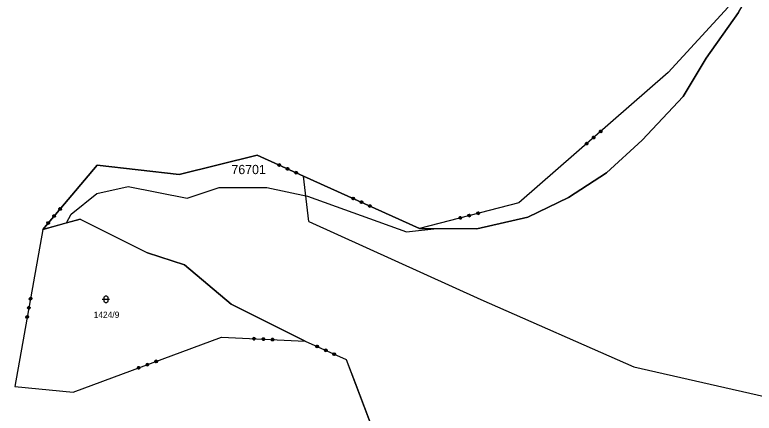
# Model space of a CAD drawing. Extents: x -779618 to -776429, y -1144546 to -1143350.
# Drawn here: x -779618.2 to -779418.1, y -1143697.1 to -1143589.4 of the extents above; entities that cross this region are included whole.
import ezdxf

# ---------------------------------------------------------------- set-up
doc = ezdxf.new("R2010")
doc.units = 0
for name, color, linetype in [('1', 7, 'Continuous'), ('11', 7, 'Continuous'), ('2', 7, 'Continuous'), ('3', 7, 'Continuous')]:
    doc.layers.add(name, color=color, linetype=linetype)

msp = doc.modelspace()

# ---------------------------------------------------------------- linework, layer by layer
at = {"layer": '1'}
for p, q in [((-779425.2, -1143587.3), (-779441.4, -1143604.95)), ((-779422.4, -1143588.74), (-779431.16, -1143601.12)), ((-779431.16, -1143601.12), (-779437.37, -1143611.48)), ((-779441.4, -1143604.95), (-779481.8, -1143640.2)), ((-779437.37, -1143611.48), (-779448.47, -1143623.31)), ((-779448.47, -1143623.31), (-779458.09, -1143632.15)), ((-779552.66, -1143627.32), (-779573.76, -1143632.55)), ((-779540.12, -1143632.98), (-779552.66, -1143627.32)), ((-779595.99, -1143630.06), (-779610.61, -1143647.4)), ((-779573.76, -1143632.55), (-779595.99, -1143630.06)), ((-779458.09, -1143632.15), (-779468.43, -1143638.83)), ((-779538.66, -1143645.32), (-779540.12, -1143632.98)), ((-779508.7, -1143647.15), (-779540.12, -1143632.98)), ((-779481.8, -1143640.2), (-779508.7, -1143647.15)), ((-779468.43, -1143638.83), (-779479.43, -1143644.1)), ((-779600.56, -1143644.61), (-779610.61, -1143647.4)), ((-779600.56, -1143644.61), (-779582.3, -1143653.77)), ((-779479.43, -1143644.1), (-779493.22, -1143647.23)), ((-779538.66, -1143645.32), (-779492.08, -1143666.42)), ((-779610.61, -1143647.4), (-779618.24, -1143689.87)), ((-779493.22, -1143647.23), (-779508.7, -1143647.15)), ((-779572.35, -1143657.01), (-779582.3, -1143653.77)), ((-779559.66, -1143667.6), (-779572.35, -1143657.01)), ((-779492.08, -1143666.42), (-779450.72, -1143684.57)), ((-779539.64, -1143677.6), (-779559.66, -1143667.6)), ((-779602.41, -1143691.41), (-779562.33, -1143676.57)), ((-779562.33, -1143676.57), (-779539.64, -1143677.6)), ((-779539.64, -1143677.6), (-779528.56, -1143682.63)), ((-779528.56, -1143682.63), (-779512.43, -1143724.88)), ((-779450.72, -1143684.57), (-779404.2, -1143695.11)), ((-779618.24, -1143689.87), (-779602.41, -1143691.41))]:
    msp.add_line(p, q, dxfattribs=at)
for points in [[(-779459.6, -1143621.26), (-779459.87, -1143621.24), (-779460.05, -1143621.04), (-779460.03, -1143620.77), (-779459.83, -1143620.59), (-779459.56, -1143620.61), (-779459.38, -1143620.81), (-779459.4, -1143621.08), (-779459.6, -1143621.26), (-779459.64, -1143621.23), (-779459.46, -1143621.08), (-779459.45, -1143620.96), (-779459.75, -1143621.23), (-779459.85, -1143621.21), (-779459.44, -1143620.85), (-779459.49, -1143620.79), (-779459.89, -1143621.14), (-779459.95, -1143621.09), (-779459.55, -1143620.74), (-779459.61, -1143620.68), (-779460.01, -1143621.03), (-779460.02, -1143620.93), (-779459.7, -1143620.65), (-779459.8, -1143620.63), (-779460.01, -1143620.82)], [(-779461.5, -1143622.91), (-779461.76, -1143622.89), (-779461.94, -1143622.69), (-779461.92, -1143622.42), (-779461.72, -1143622.24), (-779461.45, -1143622.26), (-779461.27, -1143622.46), (-779461.29, -1143622.73), (-779461.5, -1143622.91), (-779461.51, -1143622.87), (-779461.33, -1143622.71), (-779461.33, -1143622.6), (-779461.63, -1143622.86), (-779461.74, -1143622.86), (-779461.32, -1143622.49), (-779461.37, -1143622.43), (-779461.79, -1143622.8), (-779461.84, -1143622.74), (-779461.42, -1143622.37), (-779461.48, -1143622.31), (-779461.9, -1143622.68), (-779461.89, -1143622.56), (-779461.59, -1143622.3), (-779461.7, -1143622.29), (-779461.88, -1143622.45)], [(-779463.39, -1143624.56), (-779463.65, -1143624.54), (-779463.83, -1143624.34), (-779463.81, -1143624.07), (-779463.61, -1143623.89), (-779463.34, -1143623.91), (-779463.16, -1143624.11), (-779463.18, -1143624.38), (-779463.39, -1143624.56), (-779463.38, -1143624.5), (-779463.2, -1143624.34), (-779463.21, -1143624.24), (-779463.5, -1143624.49), (-779463.61, -1143624.49), (-779463.22, -1143624.14), (-779463.27, -1143624.08), (-779463.66, -1143624.43), (-779463.71, -1143624.37), (-779463.32, -1143624.02), (-779463.37, -1143623.96), (-779463.76, -1143624.3), (-779463.78, -1143624.21), (-779463.47, -1143623.94), (-779463.56, -1143623.92), (-779463.74, -1143624.07)], [(-779546.95, -1143630.25), (-779547.05, -1143630), (-779546.94, -1143629.75), (-779546.68, -1143629.66), (-779546.44, -1143629.77), (-779546.34, -1143630.02), (-779546.45, -1143630.26), (-779546.71, -1143630.36), (-779546.95, -1143630.25), (-779546.9, -1143630.23), (-779546.68, -1143630.33), (-779546.59, -1143630.28), (-779546.94, -1143630.12), (-779546.98, -1143630.02), (-779546.5, -1143630.23), (-779546.47, -1143630.16), (-779546.95, -1143629.94), (-779546.91, -1143629.87), (-779546.44, -1143630.09), (-779546.4, -1143630.02), (-779546.87, -1143629.8), (-779546.8, -1143629.75), (-779546.43, -1143629.91), (-779546.44, -1143629.82), (-779546.66, -1143629.72)], [(-779544.66, -1143631.28), (-779544.76, -1143631.03), (-779544.65, -1143630.78), (-779544.4, -1143630.69), (-779544.15, -1143630.8), (-779544.05, -1143631.05), (-779544.17, -1143631.3), (-779544.42, -1143631.39), (-779544.66, -1143631.28), (-779544.64, -1143631.25), (-779544.42, -1143631.35), (-779544.31, -1143631.31), (-779544.68, -1143631.14), (-779544.72, -1143631.04), (-779544.21, -1143631.27), (-779544.17, -1143631.19), (-779544.68, -1143630.96), (-779544.65, -1143630.89), (-779544.14, -1143631.12), (-779544.11, -1143631.05), (-779544.62, -1143630.82), (-779544.51, -1143630.78), (-779544.15, -1143630.94), (-779544.19, -1143630.84), (-779544.41, -1143630.74)], [(-779542.37, -1143632.31), (-779542.47, -1143632.06), (-779542.36, -1143631.81), (-779542.11, -1143631.72), (-779541.86, -1143631.83), (-779541.77, -1143632.08), (-779541.88, -1143632.33), (-779542.13, -1143632.42), (-779542.37, -1143632.31), (-779542.37, -1143632.27), (-779542.15, -1143632.37), (-779542.04, -1143632.33), (-779542.41, -1143632.17), (-779542.43, -1143632.07), (-779541.94, -1143632.29), (-779541.9, -1143632.22), (-779542.39, -1143632), (-779542.36, -1143631.92), (-779541.88, -1143632.14), (-779541.85, -1143632.07), (-779542.33, -1143631.85), (-779542.25, -1143631.8), (-779541.86, -1143631.97), (-779541.89, -1143631.87), (-779542.15, -1143631.76)], [(-779526.96, -1143639.27), (-779527.05, -1143639.02), (-779526.94, -1143638.77), (-779526.69, -1143638.67), (-779526.44, -1143638.79), (-779526.35, -1143639.04), (-779526.46, -1143639.28), (-779526.71, -1143639.38), (-779526.96, -1143639.27), (-779526.9, -1143639.25), (-779526.69, -1143639.35), (-779526.6, -1143639.3), (-779526.94, -1143639.14), (-779526.98, -1143639.04), (-779526.51, -1143639.25), (-779526.48, -1143639.18), (-779526.95, -1143638.96), (-779526.92, -1143638.89), (-779526.44, -1143639.1), (-779526.4, -1143639.03), (-779526.88, -1143638.82), (-779526.81, -1143638.76), (-779526.43, -1143638.93), (-779526.45, -1143638.84), (-779526.67, -1143638.74)], [(-779524.67, -1143640.3), (-779524.76, -1143640.05), (-779524.65, -1143639.8), (-779524.4, -1143639.71), (-779524.16, -1143639.82), (-779524.06, -1143640.07), (-779524.17, -1143640.32), (-779524.42, -1143640.41), (-779524.67, -1143640.3), (-779524.64, -1143640.27), (-779524.42, -1143640.37), (-779524.32, -1143640.33), (-779524.68, -1143640.16), (-779524.72, -1143640.06), (-779524.21, -1143640.29), (-779524.18, -1143640.21), (-779524.69, -1143639.98), (-779524.66, -1143639.91), (-779524.15, -1143640.14), (-779524.11, -1143640.07), (-779524.63, -1143639.84), (-779524.52, -1143639.8), (-779524.15, -1143639.96), (-779524.19, -1143639.85), (-779524.41, -1143639.76)], [(-779605.81, -1143642.2), (-779606.08, -1143642.22), (-779606.28, -1143642.05), (-779606.31, -1143641.78), (-779606.13, -1143641.58), (-779605.86, -1143641.55), (-779605.66, -1143641.73), (-779605.63, -1143641.99), (-779605.81, -1143642.2), (-779605.85, -1143642.18), (-779605.69, -1143642), (-779605.7, -1143641.89), (-779605.96, -1143642.19), (-779606.06, -1143642.19), (-779605.71, -1143641.77), (-779605.77, -1143641.72), (-779606.11, -1143642.13), (-779606.18, -1143642.08), (-779605.84, -1143641.68), (-779605.9, -1143641.63), (-779606.24, -1143642.03), (-779606.27, -1143641.94), (-779605.99, -1143641.61), (-779606.1, -1143641.62), (-779606.28, -1143641.83)], [(-779522.38, -1143641.33), (-779522.48, -1143641.08), (-779522.37, -1143640.83), (-779522.11, -1143640.74), (-779521.87, -1143640.85), (-779521.77, -1143641.1), (-779521.88, -1143641.35), (-779522.13, -1143641.44), (-779522.38, -1143641.33), (-779522.37, -1143641.29), (-779522.15, -1143641.39), (-779522.05, -1143641.35), (-779522.41, -1143641.18), (-779522.44, -1143641.09), (-779521.94, -1143641.31), (-779521.91, -1143641.24), (-779522.39, -1143641.02), (-779522.37, -1143640.94), (-779521.89, -1143641.16), (-779521.85, -1143641.09), (-779522.34, -1143640.87), (-779522.26, -1143640.82), (-779521.87, -1143640.99), (-779521.9, -1143640.89), (-779522.15, -1143640.78)], [(-779607.43, -1143644.12), (-779607.69, -1143644.14), (-779607.9, -1143643.97), (-779607.92, -1143643.7), (-779607.75, -1143643.49), (-779607.48, -1143643.47), (-779607.27, -1143643.65), (-779607.25, -1143643.91), (-779607.43, -1143644.12), (-779607.45, -1143644.09), (-779607.3, -1143643.9), (-779607.31, -1143643.79), (-779607.56, -1143644.1), (-779607.68, -1143644.11), (-779607.31, -1143643.68), (-779607.38, -1143643.63), (-779607.74, -1143644.05), (-779607.8, -1143644), (-779607.44, -1143643.57), (-779607.5, -1143643.52), (-779607.86, -1143643.95), (-779607.87, -1143643.84), (-779607.61, -1143643.53), (-779607.72, -1143643.54), (-779607.88, -1143643.73)], [(-779497.74, -1143644.65), (-779497.97, -1143644.51), (-779498.03, -1143644.25), (-779497.9, -1143644.02), (-779497.64, -1143643.95), (-779497.41, -1143644.09), (-779497.34, -1143644.35), (-779497.47, -1143644.58), (-779497.74, -1143644.65), (-779497.71, -1143644.6), (-779497.47, -1143644.54), (-779497.44, -1143644.45), (-779497.8, -1143644.54), (-779497.9, -1143644.48), (-779497.4, -1143644.35), (-779497.42, -1143644.28), (-779497.92, -1143644.41), (-779497.94, -1143644.33), (-779497.44, -1143644.2), (-779497.45, -1143644.12), (-779497.95, -1143644.25), (-779497.93, -1143644.16), (-779497.54, -1143644.06), (-779497.61, -1143643.99), (-779497.84, -1143644.05)], [(-779495.31, -1143644.02), (-779495.54, -1143643.88), (-779495.6, -1143643.62), (-779495.47, -1143643.39), (-779495.21, -1143643.32), (-779494.98, -1143643.46), (-779494.91, -1143643.72), (-779495.04, -1143643.95), (-779495.31, -1143644.02), (-779495.31, -1143643.98), (-779495.07, -1143643.92), (-779495.02, -1143643.82), (-779495.4, -1143643.92), (-779495.5, -1143643.86), (-779494.96, -1143643.72), (-779494.98, -1143643.65), (-779495.52, -1143643.79), (-779495.54, -1143643.71), (-779495, -1143643.57), (-779495.02, -1143643.49), (-779495.56, -1143643.63), (-779495.5, -1143643.53), (-779495.12, -1143643.43), (-779495.21, -1143643.38), (-779495.45, -1143643.44)], [(-779492.88, -1143643.39), (-779493.11, -1143643.26), (-779493.17, -1143643), (-779493.04, -1143642.76), (-779492.78, -1143642.7), (-779492.54, -1143642.83), (-779492.48, -1143643.09), (-779492.61, -1143643.33), (-779492.88, -1143643.39), (-779492.89, -1143643.36), (-779492.66, -1143643.3), (-779492.6, -1143643.2), (-779492.99, -1143643.3), (-779493.07, -1143643.24), (-779492.55, -1143643.1), (-779492.57, -1143643.02), (-779493.08, -1143643.16), (-779493.11, -1143643.08), (-779492.6, -1143642.95), (-779492.62, -1143642.87), (-779493.13, -1143643), (-779493.1, -1143642.91), (-779492.69, -1143642.81), (-779492.77, -1143642.75), (-779493.04, -1143642.82)], [(-779609.04, -1143646.04), (-779609.31, -1143646.06), (-779609.52, -1143645.89), (-779609.54, -1143645.62), (-779609.37, -1143645.41), (-779609.1, -1143645.39), (-779608.89, -1143645.56), (-779608.87, -1143645.83), (-779609.04, -1143646.04), (-779609.05, -1143645.98), (-779608.89, -1143645.8), (-779608.92, -1143645.7), (-779609.16, -1143645.99), (-779609.27, -1143646), (-779608.94, -1143645.6), (-779609, -1143645.55), (-779609.34, -1143645.95), (-779609.4, -1143645.9), (-779609.06, -1143645.5), (-779609.12, -1143645.44), (-779609.45, -1143645.84), (-779609.49, -1143645.76), (-779609.22, -1143645.44), (-779609.32, -1143645.43), (-779609.47, -1143645.61)], [(-779613.69, -1143666.36), (-779613.91, -1143666.51), (-779614.18, -1143666.46), (-779614.33, -1143666.24), (-779614.28, -1143665.98), (-779614.06, -1143665.82), (-779613.8, -1143665.87), (-779613.64, -1143666.09), (-779613.69, -1143666.36), (-779613.73, -1143666.36), (-779613.69, -1143666.13), (-779613.76, -1143666.03), (-779613.83, -1143666.43), (-779613.92, -1143666.47), (-779613.82, -1143665.94), (-779613.9, -1143665.93), (-779613.99, -1143666.45), (-779614.07, -1143666.44), (-779613.98, -1143665.92), (-779614.06, -1143665.91), (-779614.15, -1143666.43), (-779614.22, -1143666.37), (-779614.15, -1143665.94), (-779614.24, -1143666), (-779614.29, -1143666.27)], [(-779614.13, -1143668.83), (-779614.36, -1143668.98), (-779614.62, -1143668.94), (-779614.77, -1143668.71), (-779614.73, -1143668.45), (-779614.51, -1143668.3), (-779614.24, -1143668.34), (-779614.09, -1143668.56), (-779614.13, -1143668.83), (-779614.17, -1143668.81), (-779614.13, -1143668.58), (-779614.19, -1143668.48), (-779614.27, -1143668.88), (-779614.36, -1143668.94), (-779614.26, -1143668.39), (-779614.34, -1143668.38), (-779614.44, -1143668.93), (-779614.52, -1143668.91), (-779614.42, -1143668.36), (-779614.5, -1143668.35), (-779614.59, -1143668.9), (-779614.66, -1143668.81), (-779614.59, -1143668.41), (-779614.68, -1143668.48), (-779614.72, -1143668.71)], [(-779614.58, -1143671.3), (-779614.8, -1143671.45), (-779615.06, -1143671.41), (-779615.22, -1143671.19), (-779615.17, -1143670.92), (-779614.95, -1143670.77), (-779614.68, -1143670.81), (-779614.53, -1143671.03), (-779614.58, -1143671.3), (-779614.61, -1143671.25), (-779614.57, -1143671.02), (-779614.64, -1143670.94), (-779614.7, -1143671.32), (-779614.8, -1143671.38), (-779614.7, -1143670.87), (-779614.78, -1143670.86), (-779614.87, -1143671.37), (-779614.95, -1143671.35), (-779614.86, -1143670.84), (-779614.94, -1143670.82), (-779615.03, -1143671.33), (-779615.1, -1143671.28), (-779615.03, -1143670.87), (-779615.12, -1143670.91), (-779615.16, -1143671.14)], [(-779553.34, -1143676.66), (-779553.16, -1143676.86), (-779553.17, -1143677.13), (-779553.37, -1143677.31), (-779553.64, -1143677.3), (-779553.82, -1143677.1), (-779553.81, -1143676.83), (-779553.61, -1143676.65), (-779553.34, -1143676.66), (-779553.33, -1143676.7), (-779553.57, -1143676.69), (-779553.65, -1143676.76), (-779553.25, -1143676.78), (-779553.2, -1143676.86), (-779553.74, -1143676.84), (-779553.74, -1143676.92), (-779553.21, -1143676.94), (-779553.2, -1143677.02), (-779553.73, -1143677), (-779553.74, -1143677.08), (-779553.21, -1143677.1), (-779553.26, -1143677.18), (-779553.69, -1143677.16), (-779553.62, -1143677.25), (-779553.35, -1143677.26)], [(-779550.83, -1143676.77), (-779550.65, -1143676.97), (-779550.66, -1143677.24), (-779550.86, -1143677.42), (-779551.13, -1143677.41), (-779551.31, -1143677.21), (-779551.3, -1143676.94), (-779551.1, -1143676.76), (-779550.83, -1143676.77), (-779550.84, -1143676.81), (-779551.08, -1143676.8), (-779551.17, -1143676.88), (-779550.77, -1143676.89), (-779550.69, -1143676.98), (-779551.25, -1143676.95), (-779551.25, -1143677.03), (-779550.69, -1143677.06), (-779550.7, -1143677.14), (-779551.26, -1143677.11), (-779551.26, -1143677.19), (-779550.7, -1143677.22), (-779550.78, -1143677.29), (-779551.18, -1143677.28), (-779551.11, -1143677.36), (-779550.87, -1143677.37)], [(-779548.32, -1143676.89), (-779548.14, -1143677.08), (-779548.15, -1143677.35), (-779548.35, -1143677.53), (-779548.62, -1143677.52), (-779548.8, -1143677.32), (-779548.79, -1143677.05), (-779548.59, -1143676.87), (-779548.32, -1143676.89), (-779548.37, -1143676.92), (-779548.6, -1143676.91), (-779548.67, -1143676.99), (-779548.29, -1143677.01), (-779548.21, -1143677.09), (-779548.73, -1143677.07), (-779548.74, -1143677.15), (-779548.22, -1143677.17), (-779548.22, -1143677.25), (-779548.74, -1143677.23), (-779548.75, -1143677.31), (-779548.23, -1143677.33), (-779548.28, -1143677.41), (-779548.69, -1143677.39), (-779548.64, -1143677.47), (-779548.4, -1143677.48)], [(-779536.13, -1143678.84), (-779536.03, -1143679.1), (-779536.14, -1143679.34), (-779536.39, -1143679.44), (-779536.64, -1143679.32), (-779536.73, -1143679.07), (-779536.62, -1143678.83), (-779536.37, -1143678.73), (-779536.13, -1143678.84), (-779536.13, -1143678.88), (-779536.35, -1143678.79), (-779536.46, -1143678.82), (-779536.09, -1143678.99), (-779536.07, -1143679.09), (-779536.56, -1143678.86), (-779536.6, -1143678.94), (-779536.11, -1143679.16), (-779536.14, -1143679.23), (-779536.62, -1143679.01), (-779536.65, -1143679.09), (-779536.17, -1143679.31), (-779536.25, -1143679.36), (-779536.64, -1143679.18), (-779536.61, -1143679.28), (-779536.36, -1143679.4)], [(-779533.84, -1143679.88), (-779533.75, -1143680.13), (-779533.86, -1143680.38), (-779534.11, -1143680.47), (-779534.35, -1143680.36), (-779534.45, -1143680.11), (-779534.34, -1143679.86), (-779534.09, -1143679.77), (-779533.84, -1143679.88), (-779533.87, -1143679.91), (-779534.08, -1143679.81), (-779534.19, -1143679.85), (-779533.83, -1143680.02), (-779533.79, -1143680.13), (-779534.3, -1143679.89), (-779534.33, -1143679.97), (-779533.82, -1143680.2), (-779533.85, -1143680.27), (-779534.36, -1143680.04), (-779534.4, -1143680.11), (-779533.89, -1143680.34), (-779533.99, -1143680.38), (-779534.36, -1143680.22), (-779534.32, -1143680.32), (-779534.1, -1143680.42)], [(-779531.55, -1143680.92), (-779531.46, -1143681.17), (-779531.57, -1143681.42), (-779531.82, -1143681.51), (-779532.07, -1143681.4), (-779532.16, -1143681.15), (-779532.05, -1143680.9), (-779531.8, -1143680.81), (-779531.55, -1143680.92), (-779531.61, -1143680.94), (-779531.83, -1143680.84), (-779531.91, -1143680.89), (-779531.57, -1143681.04), (-779531.53, -1143681.15), (-779532, -1143680.94), (-779532.03, -1143681.01), (-779531.56, -1143681.22), (-779531.59, -1143681.3), (-779532.07, -1143681.08), (-779532.11, -1143681.15), (-779531.64, -1143681.37), (-779531.71, -1143681.42), (-779532.08, -1143681.25), (-779532.07, -1143681.35), (-779531.85, -1143681.44)], [(-779584.7, -1143684.51), (-779584.46, -1143684.63), (-779584.37, -1143684.88), (-779584.48, -1143685.12), (-779584.73, -1143685.22), (-779584.97, -1143685.1), (-779585.07, -1143684.85), (-779584.96, -1143684.61), (-779584.7, -1143684.51), (-779584.68, -1143684.55), (-779584.91, -1143684.63), (-779584.95, -1143684.73), (-779584.58, -1143684.59), (-779584.49, -1143684.65), (-779585, -1143684.84), (-779584.97, -1143684.91), (-779584.47, -1143684.73), (-779584.44, -1143684.8), (-779584.93, -1143684.98), (-779584.91, -1143685.06), (-779584.41, -1143684.87), (-779584.43, -1143684.97), (-779584.83, -1143685.12), (-779584.74, -1143685.17), (-779584.48, -1143685.07)], [(-779582.35, -1143683.64), (-779582.11, -1143683.75), (-779582.01, -1143684.01), (-779582.12, -1143684.25), (-779582.38, -1143684.34), (-779582.62, -1143684.23), (-779582.72, -1143683.98), (-779582.6, -1143683.74), (-779582.35, -1143683.64), (-779582.35, -1143683.68), (-779582.57, -1143683.77), (-779582.62, -1143683.87), (-779582.24, -1143683.73), (-779582.14, -1143683.78), (-779582.66, -1143683.97), (-779582.64, -1143684.05), (-779582.11, -1143683.85), (-779582.08, -1143683.93), (-779582.61, -1143684.12), (-779582.58, -1143684.2), (-779582.06, -1143684), (-779582.1, -1143684.1), (-779582.48, -1143684.24), (-779582.38, -1143684.29), (-779582.15, -1143684.21)], [(-779580, -1143682.77), (-779579.75, -1143682.88), (-779579.66, -1143683.13), (-779579.77, -1143683.38), (-779580.02, -1143683.47), (-779580.27, -1143683.36), (-779580.36, -1143683.11), (-779580.25, -1143682.86), (-779580, -1143682.77), (-779580.02, -1143682.82), (-779580.25, -1143682.9), (-779580.27, -1143683), (-779579.92, -1143682.87), (-779579.81, -1143682.91), (-779580.3, -1143683.1), (-779580.27, -1143683.17), (-779579.79, -1143682.99), (-779579.76, -1143683.06), (-779580.25, -1143683.25), (-779580.23, -1143683.32), (-779579.74, -1143683.14), (-779579.75, -1143683.23), (-779580.13, -1143683.37), (-779580.06, -1143683.43), (-779579.83, -1143683.35)]]:
    msp.add_lwpolyline(points, dxfattribs=at)
at = {"layer": '11'}
for p, q in [((-779610.61, -1143647.4), (-779604.21, -1143645.62)), ((-779508.7, -1143647.15), (-779504, -1143647.17))]:
    msp.add_line(p, q, dxfattribs=at)
for points in [[(-779504, -1143647.17), (-779493.22, -1143647.23), (-779479.43, -1143644.1), (-779468.43, -1143638.83), (-779458.09, -1143632.15), (-779448.47, -1143623.31), (-779437.37, -1143611.48), (-779431.16, -1143601.12), (-779422.4, -1143588.74), (-779415.75, -1143577.19), (-779400.9, -1143559.45), (-779392.76, -1143549.06), (-779386.97, -1143535.53), (-779385.43, -1143521.63), (-779387.33, -1143510.67), (-779392.06, -1143472.65), (-779395.24, -1143443.6), (-779375.19, -1143466.02), (-779355.63, -1143474.84), (-779348.5, -1143502.34), (-779332.68, -1143501.03), (-779317.8, -1143497.23), (-779309.71, -1143489.68), (-779287.14, -1143495.83)], [(-779610.61, -1143647.4), (-779595.99, -1143630.06), (-779573.76, -1143632.55), (-779552.66, -1143627.32), (-779540.12, -1143632.98), (-779508.7, -1143647.15)], [(-779604.21, -1143645.62), (-779602.96, -1143643.32), (-779596.02, -1143637.75), (-779587.54, -1143635.8), (-779571.62, -1143638.98), (-779562.9, -1143636.07), (-779550.04, -1143636.07), (-779539.05, -1143638.45), (-779512.28, -1143648.04), (-779504, -1143647.17)], [(-779604.21, -1143645.62), (-779600.56, -1143644.61), (-779582.3, -1143653.77), (-779572.35, -1143657.01), (-779559.66, -1143667.6), (-779539.64, -1143677.6)], [(-779539.64, -1143677.6), (-779528.56, -1143682.63), (-779526.17, -1143688.88), (-779518.24, -1143709.67), (-779512.43, -1143724.88), (-779506.83, -1143749.88), (-779507.88, -1143751.15)]]:
    msp.add_lwpolyline(points, dxfattribs=at)
at = {"layer": '3'}
msp.add_lwpolyline([(-779594.58, -1143666.32), (-779593.31, -1143666.32), (-779592.58, -1143666.32)], dxfattribs=at)
msp.add_lwpolyline([(-779594.08, -1143665.82), (-779593.98, -1143665.53), (-779593.73, -1143665.35), (-779593.42, -1143665.35), (-779593.17, -1143665.53), (-779593.07, -1143665.82), (-779593.07, -1143666.82), (-779593.17, -1143667.11), (-779593.42, -1143667.29), (-779593.73, -1143667.29), (-779593.98, -1143667.11), (-779594.08, -1143666.82)], close=True, dxfattribs=at)

# ---------------------------------------------------------------- texts
at = {"layer": '11'}
msp.add_text('76701', height=2.5, dxfattribs=at).set_placement((-779559.61, -1143632.47))
at = {"layer": '2'}
msp.add_text('1424/9', height=1.7, dxfattribs=at).set_placement((-779596.9, -1143671.35))

doc.saveas('drawing.dxf')
